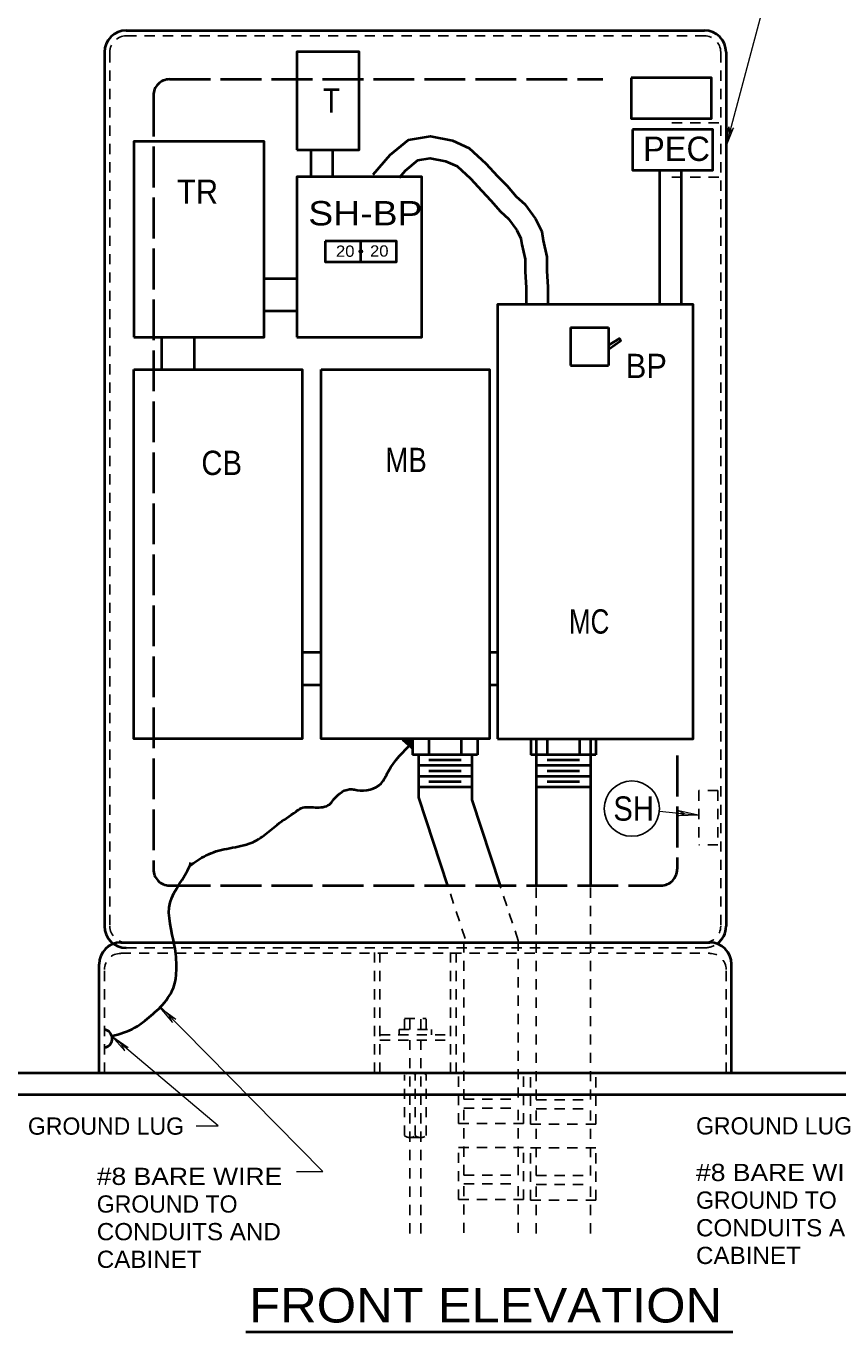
# Model space of a CAD drawing. Extents: x 312583 to 312854, y 144419 to 144597.
# Drawn here: x 312768.4 to 312804.2, y 144509.4 to 144567 of the extents above; entities that cross this region are included whole.
import ezdxf
from ezdxf.enums import TextEntityAlignment as Align

# ---------------------------------------------------------------- set-up
doc = ezdxf.new("R2010")
doc.units = 0
doc.header["$LTSCALE"] = 0.3
doc.header["$PDMODE"] = 32
doc.header["$PDSIZE"] = 0.15
doc.linetypes.add('LONG_DASHED', pattern=[7.5, 6, -1.5])
doc.linetypes.add('SHORT_DASHED', pattern=[2.7, 1.5, -1.2])
doc.layers.add('1', color=7, linetype='Continuous', lineweight=25)
doc.layers.add('2', color=7, linetype='Continuous', lineweight=13)

msp = doc.modelspace()

# ---------------------------------------------------------------- linework, layer by layer
at = {"layer": '1', "lineweight": 40}
for p, q in [((312772.801, 144566.8256), (312798.3157, 144566.8256)), ((312771.8427, 144565.8673), (312771.8427, 144527.2963)), ((312799.274, 144565.8673), (312799.274, 144527.2963)), ((312792.4047, 144553.7233), (312792.4047, 144552.0443)), ((312792.4047, 144553.7233), (312794.0837, 144553.7233)), ((312794.0837, 144553.7233), (312794.0837, 144552.0443)), ((312792.4047, 144552.0443), (312794.0837, 144552.0443)), ((312785.4357, 144535.584), (312785.4357, 144534.8633)), ((312786.1563, 144535.584), (312786.1563, 144534.8633)), ((312787.59, 144535.584), (312787.59, 144534.8633)), ((312788.3107, 144535.584), (312788.3107, 144534.8633)), ((312790.6567, 144535.584), (312790.6567, 144534.8633)), ((312790.8943, 144535.5916), (312790.8943, 144529.098)), ((312791.3773, 144535.584), (312791.3773, 144534.8633)), ((312792.811, 144535.584), (312792.811, 144534.8633)), ((312793.2863, 144535.5916), (312793.2863, 144529.098)), ((312793.5317, 144535.584), (312793.5317, 144534.8633)), ((312788.3107, 144534.8633), (312785.4357, 144534.8633)), ((312785.704, 144534.8863), (312785.704, 144532.9696)), ((312787.59, 144534.6256), (312786.1563, 144534.6256)), ((312788.05, 144534.8863), (312788.05, 144532.8776)), ((312793.5317, 144534.8633), (312790.6567, 144534.8633)), ((312792.811, 144534.6256), (312791.3773, 144534.6256)), ((312788.073, 144534.388), (312785.6733, 144534.388)), ((312788.073, 144533.905), (312785.6733, 144533.905)), ((312787.59, 144534.1426), (312786.1563, 144534.1426)), ((312793.294, 144534.388), (312790.8943, 144534.388)), ((312793.294, 144533.905), (312790.8943, 144533.905)), ((312792.811, 144534.1426), (312791.3773, 144534.1426)), ((312788.073, 144533.4296), (312785.6733, 144533.4296)), ((312787.59, 144533.6673), (312786.1563, 144533.6673)), ((312793.294, 144533.4296), (312790.8943, 144533.4296)), ((312792.811, 144533.6673), (312791.3773, 144533.6673)), ((312772.5633, 144526.5756), (312798.561, 144526.5756)), ((312771.605, 144520.8256), (312771.605, 144525.6173)), ((312799.5193, 144520.8256), (312799.5193, 144525.6173))]:
    msp.add_line(p, q, dxfattribs=at)
at = {"layer": '1', "linetype": 'SHORT_DASHED'}
for p, q in [((312772.801, 144566.588), (312798.3157, 144566.588)), ((312772.088, 144565.8673), (312772.088, 144527.2963)), ((312799.0363, 144565.8673), (312799.0363, 144527.2963)), ((312796.882, 144562.7546), (312799.0363, 144562.7546)), ((312796.882, 144560.355), (312799.0363, 144560.355)), ((312798.9137, 144533.284), (312798.078, 144533.284)), ((312798.078, 144533.284), (312798.078, 144530.892)), ((312798.9137, 144533.284), (312798.9137, 144530.892)), ((312798.9137, 144530.892), (312798.078, 144530.892)), ((312790.8943, 144529.811), (312790.8943, 144519.6373)), ((312793.2863, 144529.811), (312793.2863, 144519.6373)), ((312772.801, 144526.5756), (312798.3157, 144526.5756)), ((312787.705, 144526.5833), (312787.705, 144519.6603)), ((312790.1047, 144526.66), (312790.1047, 144519.6603)), ((312772.5633, 144526.1003), (312798.561, 144526.1003)), ((312772.801, 144526.338), (312798.3157, 144526.338)), ((312783.7643, 144520.8256), (312783.7643, 144526.338)), ((312784.002, 144520.8256), (312784.002, 144526.338)), ((312787.1147, 144520.8256), (312787.1147, 144526.338)), ((312787.36, 144520.8256), (312787.36, 144526.338)), ((312771.8427, 144520.8256), (312771.8427, 144525.3796)), ((312799.274, 144520.8256), (312799.274, 144525.3796)), ((312785.3207, 144522.7423), (312785.3207, 144523.2253)), ((312785.8037, 144522.7423), (312785.8037, 144523.2253)), ((312786.0413, 144522.7423), (312786.0413, 144523.2253)), ((312784.002, 144522.5046), (312787.1147, 144522.5046)), ((312784.8453, 144522.7423), (312786.279, 144522.7423)), ((312784.8453, 144522.5046), (312784.8453, 144522.7423)), ((312786.279, 144522.5046), (312786.279, 144522.7423)), ((312784.002, 144522.267), (312787.1147, 144522.267)), ((312785.3207, 144513.734), (312785.3207, 144522.267)), ((312785.8037, 144513.734), (312785.8037, 144522.267)), ((312785.083, 144518.0503), (312785.083, 144520.7413)), ((312785.5583, 144518.0503), (312785.5583, 144520.8256)), ((312786.0413, 144518.0503), (312786.0413, 144520.7413)), ((312787.4673, 144518.587), (312787.4673, 144520.8563)), ((312790.3423, 144518.587), (312790.3423, 144520.8563)), ((312790.649, 144518.5563), (312790.649, 144520.8256)), ((312793.524, 144518.5563), (312793.524, 144520.8256)), ((312787.705, 144519.6603), (312790.1047, 144519.6603)), ((312790.8943, 144519.6373), (312793.2863, 144519.6373)), ((312787.705, 144519.2693), (312790.1047, 144519.2693)), ((312787.705, 144516.31), (312787.705, 144519.2693)), ((312790.1047, 144516.31), (312790.1047, 144519.2693)), ((312790.8943, 144519.2386), (312793.2863, 144519.2386)), ((312790.8943, 144516.287), (312790.8943, 144519.2386)), ((312793.2863, 144516.287), (312793.2863, 144519.2386)), ((312787.4673, 144518.587), (312790.3423, 144518.587)), ((312790.649, 144518.5563), (312793.524, 144518.5563)), ((312785.8037, 144517.9736), (312785.3207, 144517.9736)), ((312787.4673, 144517.529), (312790.3423, 144517.529)), ((312787.4673, 144515.229), (312787.4673, 144517.529)), ((312790.3423, 144515.229), (312790.3423, 144517.529)), ((312790.649, 144517.506), (312793.524, 144517.506)), ((312790.649, 144515.206), (312790.649, 144517.506)), ((312793.524, 144515.206), (312793.524, 144517.506)), ((312787.705, 144516.31), (312790.1047, 144516.31)), ((312790.8943, 144516.287), (312793.2863, 144516.287)), ((312787.705, 144515.919), (312790.1047, 144515.919)), ((312787.705, 144513.757), (312787.705, 144515.919)), ((312790.1047, 144513.757), (312790.1047, 144515.919)), ((312790.8943, 144515.8883), (312793.2863, 144515.8883)), ((312790.8943, 144513.734), (312790.8943, 144515.8883)), ((312793.2863, 144513.734), (312793.2863, 144515.8883)), ((312787.4673, 144515.229), (312790.3423, 144515.229)), ((312790.649, 144515.206), (312793.524, 144515.206))]:
    msp.add_line(p, q, dxfattribs=at)
at = {"layer": '1', "linetype": 'LONG_DASHED', "lineweight": 40}
for p, q in [((312774.7177, 144564.6713), (312793.8383, 144564.6713)), ((312774.0047, 144563.9506), (312774.0047, 144529.811)), ((312797.1197, 144534.825), (312797.1197, 144529.811))]:
    msp.add_line(p, q, dxfattribs=at)
at = {"layer": '1', "lineweight": 40}
for points in [[(312794.122, 144552.949), (312794.5667, 144553.2326), (312794.6127, 144553.1176), (312794.122, 144552.7573)], [(312750.646, 144520.8256), (312769.3932, 144520.8256), (312838.4507, 144520.8256)], [(312749.6877, 144519.8673), (312769.3932, 144519.8673), (312839.409, 144519.8673)]]:
    msp.add_lwpolyline(points, dxfattribs=at)
at = {"layer": '1', "linetype": 'SHORT_DASHED'}
msp.add_lwpolyline([(312785.083, 144522.7423), (312785.083, 144523.2253), (312786.0413, 144523.2253)], dxfattribs=at)
at = {"layer": '1', "lineweight": 40}
for centre, radius, start, end in [((312772.8029, 144565.8673), 0.9583, 90, 180), ((312798.3176, 144565.8673), 0.9583, 0, 90), ((312772.8029, 144527.2944), 0.9583, 180, 270), ((312798.3176, 144527.2944), 0.9583, 306.01567, 0), ((312772.5633, 144525.6173), 0.9583, 90, 180), ((312798.5572, 144525.6173), 0.9583, 0, 90), ((312771.7792, 144522.3336), 0.4076, 285.15764, 77.61644)]:
    msp.add_arc(centre, radius, start, end, dxfattribs=at)
at = {"layer": '1', "linetype": 'SHORT_DASHED'}
for centre, radius, start, end in [((312772.8029, 144565.8673), 0.7188, 90, 180), ((312798.3176, 144565.8673), 0.7188, 0, 90), ((312772.8029, 144527.2944), 0.7188, 180, 270), ((312798.3176, 144527.2944), 0.7188, 270, 0), ((312798.3176, 144527.2944), 0.9583, 270, 306.01567), ((312772.5633, 144525.3777), 0.7188, 90, 180), ((312798.5572, 144525.3777), 0.7188, 0, 90), ((312785.3207, 144520.4379), 0.3858, 51.61151, 128.38849), ((312785.7998, 144520.4045), 0.4125, 54.49327, 125.50673), ((312785.3207, 144518.3823), 0.4125, 234.49327, 305.50673), ((312785.7998, 144518.3823), 0.4125, 234.49327, 305.50673)]:
    msp.add_arc(centre, radius, start, end, dxfattribs=at)
at = {"layer": '1', "linetype": 'LONG_DASHED', "lineweight": 40}
for centre, start, end in [((312774.7196, 144563.9506), 90, 180), ((312774.7196, 144529.81), 180, 270), ((312796.4009, 144529.81), 270, 0)]:
    msp.add_arc(centre, 0.7188, start, end, dxfattribs=at)
at = {"layer": '1', "lineweight": 40}
msp.add_spline([(312772.1723, 144522.4433), (312773.1767, 144522.8113), (312773.6367, 144523.1333), (312774.319, 144523.7313), (312774.8863, 144524.5746), (312775.0243, 144525.4486), (312774.94, 144526.43), (312774.7407, 144528.339), (312775.607, 144529.9566), (312775.6607, 144530.1023)], degree=3, dxfattribs=at)
at = {"layer": '2'}
for p, q in [((312799.274, 144561.712), (312799.3967, 144562.5783)), ((312799.274, 144561.712), (312799.6037, 144562.5246)), ((312799.3967, 144562.5783), (312799.4273, 144562.287)), ((312799.6037, 144562.5246), (312799.4273, 144562.287)), ((312784.7227, 144557.5643), (312784.7227, 144556.6903)), ((312796.33, 144532.364), (312798.0397, 144532.1953)), ((312797.1657, 144532.1723), (312797.457, 144532.2566)), ((312798.0397, 144532.1953), (312797.1657, 144532.1723)), ((312797.1887, 144532.387), (312797.457, 144532.2566)), ((312798.0397, 144532.1953), (312797.1887, 144532.387)), ((312774.2909, 144523.7122), (312774.8464, 144523.0373)), ((312774.2909, 144523.7122), (312774.9939, 144523.1961)), ((312781.4775, 144516.4633), (312774.319, 144523.7313)), ((312774.8464, 144523.0373), (312774.7169, 144523.3072)), ((312774.9939, 144523.1961), (312774.7169, 144523.3072)), ((312776.8612, 144518.4827), (312772.1723, 144522.4433)), ((312772.1723, 144522.4433), (312772.7489, 144521.7881)), ((312772.1723, 144522.4433), (312772.8897, 144521.9475)), ((312772.7489, 144521.7881), (312772.6143, 144522.0475)), ((312772.8897, 144521.9475), (312772.6143, 144522.0475)), ((312775.8952, 144518.4827), (312776.8612, 144518.4827)), ((312780.3122, 144516.4633), (312781.4775, 144516.4633))]:
    msp.add_line(p, q, dxfattribs=at)
at = {"layer": '2', "lineweight": 40}
for p, q in [((312780.966, 144560.3703), (312780.966, 144561.574)), ((312781.9243, 144560.3703), (312781.9243, 144561.574)), ((312796.3453, 144554.8043), (312796.3453, 144560.654)), ((312797.3037, 144554.8043), (312797.3037, 144560.654)), ((312783.1587, 144556.6213), (312783.1587, 144557.526)), ((312778.9037, 144555.8853), (312780.3373, 144555.8853)), ((312778.9037, 144554.4516), (312780.3373, 144554.4516)), ((312774.3803, 144551.8986), (312774.3803, 144553.3323)), ((312775.8217, 144551.8986), (312775.8217, 144553.3323)), ((312780.5903, 144539.3866), (312781.426, 144539.3866)), ((312788.855, 144539.3866), (312789.2153, 144539.3866)), ((312780.5903, 144537.953), (312781.426, 144537.953)), ((312788.855, 144537.953), (312789.2153, 144537.953)), ((312785.704, 144532.9696), (312786.9843, 144529.0826)), ((312788.05, 144532.8776), (312789.292, 144529.121)), ((312778.0847, 144509.3907), (312799.5714, 144509.3907))]:
    msp.add_line(p, q, dxfattribs=at)
at = {"layer": '2', "linetype": 'SHORT_DASHED', "lineweight": 25}
for p, q in [((312787.7587, 144526.752), (312785.704, 144532.9696)), ((312790.1047, 144526.66), (312788.05, 144532.8776))]:
    msp.add_line(p, q, dxfattribs=at)
at = {"layer": '2', "linetype": 'LONG_DASHED', "lineweight": 40}
msp.add_line((312774.7177, 144529.0903), (312796.399, 144529.0903), dxfattribs=at)
at = {"layer": '2'}
msp.add_lwpolyline([(312799.274, 144561.712), (312801.758, 144571.0423), (312800.24, 144571.0423)], dxfattribs=at)
at = {"layer": '2', "lineweight": 40}
for points in [[(312780.3297, 144561.5586), (312783.082, 144561.5586), (312783.082, 144565.875), (312780.3297, 144565.875)], [(312795.088, 144564.7326), (312795.088, 144562.9386), (312798.6377, 144562.9386), (312798.6377, 144564.7326)], [(312795.1417, 144562.4556), (312795.1417, 144560.654), (312798.6913, 144560.654), (312798.6913, 144562.4556)], [(312773.1383, 144553.294), (312778.8883, 144553.294), (312778.8883, 144561.919), (312773.1383, 144561.919)], [(312780.3297, 144553.294), (312785.842, 144553.294), (312785.842, 144560.3626), (312780.3297, 144560.3626)], [(312781.587, 144557.526), (312781.587, 144556.6213), (312784.7303, 144556.6213), (312784.7303, 144557.526)], [(312789.1923, 144535.5686), (312797.8173, 144535.5686), (312797.8173, 144554.7353), (312789.1923, 144554.7353)], [(312773.1383, 144551.8603), (312780.5673, 144551.8603), (312780.5673, 144535.5686), (312773.1383, 144535.5686)], [(312781.403, 144551.8603), (312788.832, 144551.8603), (312788.832, 144535.5686), (312781.403, 144535.5686)]]:
    msp.add_lwpolyline(points, close=True, dxfattribs=at)
for points in [[(312783.703, 144560.4623), (312784.4543, 144561.3363), (312785.2593, 144562.0033), (312786.233, 144562.1643), (312787.199, 144561.9726), (312787.9427, 144561.6353), (312788.671, 144560.9606), (312789.1847, 144560.401), (312789.614, 144559.9716), (312790.005, 144559.4963), (312790.3883, 144559.159), (312790.8637, 144558.5073), (312791.1473, 144557.9476), (312791.2087, 144557.549), (312791.362, 144556.836), (312791.362, 144556.2226), (312791.408, 144555.4943), (312791.408, 144554.6893)], [(312784.8607, 144560.332), (312785.129, 144560.6463), (312785.6733, 144561.0986), (312786.2177, 144561.1906), (312786.9, 144561.0603), (312787.406, 144560.8303), (312787.9963, 144560.286), (312788.4947, 144559.7416), (312788.901, 144559.3276), (312789.315, 144558.8293), (312789.6753, 144558.5073), (312790.0433, 144558.009), (312790.2197, 144557.6486), (312790.2657, 144557.3726), (312790.4037, 144556.7363), (312790.4037, 144556.192), (312790.4497, 144555.4636), (312790.4497, 144554.6893)], [(312784.991, 144535.5303), (312785.4127, 144535.1623), (312785.4127, 144535.2236), (312785.0983, 144535.492), (312785.3897, 144535.308), (312785.267, 144535.492), (312785.3743, 144535.3463), (312785.3743, 144535.4766), (312785.083, 144535.515)]]:
    msp.add_lwpolyline(points, dxfattribs=at)
at = {"layer": '2', "lineweight": 25}
msp.add_circle((312795.1158, 144532.4818), 1.2209, dxfattribs=at)
at = {"layer": '2', "lineweight": 40}
msp.add_spline([(312775.607, 144529.9566), (312776.3353, 144530.4243), (312777.2477, 144530.7156), (312778.229, 144530.938), (312778.8807, 144531.2983), (312779.4633, 144531.7736), (312780.299, 144532.3563), (312780.5213, 144532.502), (312781.242, 144532.5326), (312781.8247, 144532.7166), (312781.9703, 144532.9006), (312782.7753, 144533.3376), (312782.99, 144533.2993), (312784.048, 144533.5906), (312784.3777, 144534.135), (312785.428, 144535.377)], degree=3, dxfattribs=at)
at = {"layer": '2'}
msp.add_point((312783.1587, 144557.0736), dxfattribs=at)

# ---------------------------------------------------------------- texts
for s, height, width, p in [('T', 1.072, 0.85, (312781.8592, 144563.1993)), ('TR', 1.072, 0.95, (312775.952, 144559.1743)), ('SH-BP', 1.072, 1.15, (312783.358, 144558.2236)), ('20', 0.4983, 1.1, (312782.4687, 144556.836)), ('20', 0.4983, 1.1, (312783.9713, 144556.8436)), ('BP', 1.072, 0.95, (312795.755, 144551.4846)), ('MB', 1.072, 0.85, (312785.152, 144547.337)), ('CB', 1.072, 0.9, (312777.0176, 144547.2066)), ('MC', 1.072, 0.8, (312793.2326, 144540.207)), ('SH', 1.072, 0.9, (312795.1953, 144531.95)), ('FRONT ELEVATION', 1.52, 1.1, (312788.6647, 144509.8055))]:
    msp.add_text(s, height=height, dxfattribs=dict(at, width=width)).set_placement(p, align=Align.CENTER)
msp.add_text('PEC', height=1.072, dxfattribs=at).set_placement((312797.089, 144561.068), align=Align.CENTER)
for s, p in [('GROUND LUG', (312768.4661, 144518.0927)), ('GROUND LUG', (312797.9482, 144518.103)), ('GROUND TO', (312797.9483, 144514.8267)), ('GROUND TO', (312771.5052, 144514.655))]:
    msp.add_text(s, height=0.76, dxfattribs=at).set_placement(p)
for s, width, p in [('#8 BARE WIRE', 1.15, (312771.5052, 144515.875)), ('#8 BARE WIRE', 1.15, (312797.9483, 144516.0467)), ('CONDUITS AND', 1.05, (312797.9483, 144513.6067)), ('CONDUITS AND', 1.05, (312771.5052, 144513.435)), ('CABINET', 1.05, (312797.9483, 144512.3867)), ('CABINET', 1.05, (312771.5052, 144512.215))]:
    msp.add_text(s, height=0.76, dxfattribs=dict(at, width=width)).set_placement(p)

doc.saveas('drawing.dxf')
